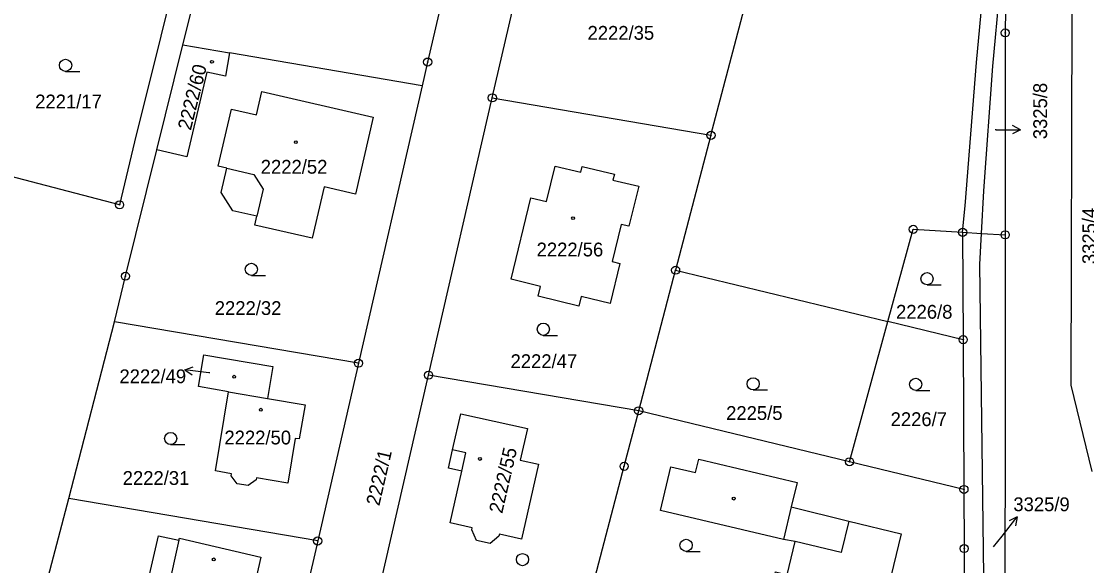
# Model space of a CAD drawing. Extents: x -733394 to -722299, y -1082822 to -1075049.
# Drawn here: x -728113.5 to -727982.2, y -1080117.1 to -1080050 of the extents above; entities that cross this region are included whole.
import ezdxf

# ---------------------------------------------------------------- set-up
doc = ezdxf.new("R2010")
doc.units = 0
for name, color, linetype in [('Hranice parcel', 7, 'Continuous'), ('Parcelní čísla', 7, 'Continuous'), ('Pop  PČ popisy', 7, 'Continuous'), ('Vnitřní kresba', 7, 'Continuous'), ('Značky bodu BP', 7, 'Continuous'), ('Značky budov', 7, 'Continuous'), ('Značky kultur', 7, 'Continuous')]:
    doc.layers.add(name, color=color, linetype=linetype)

msp = doc.modelspace()

# ---------------------------------------------------------------- linework, layer by layer
at = {"layer": 'Hranice parcel'}
for p, q in [((-728028.5, -1080064.02), (-728021.79, -1080038.43)), ((-728055.46, -1080059.4), (-728051.18, -1080040.77)), ((-728096.82, -1080065.82), (-728093.6, -1080052.86)), ((-728093.6, -1080052.86), (-728087.85, -1080053.85)), ((-728064.1, -1080057.92), (-728087.85, -1080053.85)), ((-728064.1, -1080057.92), (-728071.96, -1080092.12)), ((-728063.32, -1080093.59), (-728055.46, -1080059.4)), ((-728055.46, -1080059.4), (-728028.5, -1080064.02)), ((-728028.5, -1080064.02), (-728032.86, -1080080.65)), ((-727997.47, -1080075.98), (-727995.14, -1080076.12)), ((-727997.47, -1080075.98), (-727997.4, -1080089.22)), ((-727995.14, -1080076.12), (-727992.23, -1080076.29)), ((-728037.41, -1080097.98), (-728032.86, -1080080.65)), ((-728032.86, -1080080.65), (-728006.68, -1080086.97)), ((-728107.69, -1080108.81), (-728102.03, -1080087.02)), ((-728071.96, -1080092.12), (-728102.03, -1080087.02)), ((-728011.42, -1080104.27), (-728006.68, -1080086.97)), ((-727997.4, -1080089.22), (-728006.68, -1080086.97)), ((-727997.4, -1080089.22), (-727997.31, -1080107.68)), ((-728071.96, -1080092.12), (-728076.99, -1080114.03)), ((-728069.83, -1080121.9), (-728063.32, -1080093.59)), ((-728037.41, -1080097.98), (-728063.32, -1080093.59)), ((-728087.97, -1080095.65), (-728083.16, -1080096.46)), ((-728011.42, -1080104.27), (-728037.41, -1080097.98)), ((-727997.31, -1080107.68), (-728011.42, -1080104.27)), ((-728113.36, -1080130.56), (-728107.69, -1080108.81)), ((-728076.99, -1080114.03), (-728107.69, -1080108.81)), ((-728076.99, -1080114.03), (-728082.02, -1080135.91))]:
    msp.add_line(p, q, dxfattribs=at)
for points in [[(-727997.47, -1080075.98), (-727997.14, -1080072.72), (-727995.77, -1080055.05), (-727992.88, -1080024.23), (-727989.24, -1079986.88)], [(-728090.08, -1080026.56), (-728096.32, -1080051.79), (-728099.57, -1080064.82), (-728101.42, -1080072.59), (-728130.38, -1080065.04), (-728119.19, -1080019.31)], [(-728093.6, -1080052.86), (-728092.88, -1080049.94), (-728087.37, -1080027.23)], [(-727995.14, -1080076.12), (-727994.87, -1080070.86), (-727993.74, -1080055.5), (-727992.04, -1080036.89)], [(-727992.04, -1080036.89), (-727992.22, -1080051.39), (-727992.23, -1080076.29)], [(-728059.81, -1080039.25), (-728063.43, -1080054.99), (-728064.1, -1080057.92)], [(-727981.48, -1080105.46), (-727984.1, -1080094.81), (-727983.95, -1080048.87), (-727983.62, -1080045.49), (-727981.59, -1080043.33)], [(-728087.85, -1080053.85), (-728088.35, -1080056.74), (-728090.66, -1080056.22), (-728093.14, -1080066.68), (-728096.82, -1080065.82)], [(-728089.26, -1080067.84), (-728087.62, -1080060.78), (-728084.55, -1080061.48), (-728083.88, -1080058.61), (-728070.13, -1080061.77), (-728072.31, -1080071.26), (-728076.2, -1080070.37), (-728077.66, -1080076.69), (-728084.73, -1080075.08), (-728084.48, -1080074), (-728087.46, -1080073.32), (-728088.87, -1080071.07), (-728088.19, -1080068.08), (-728089.26, -1080067.84)], [(-728102.03, -1080087.02), (-728100.69, -1080081.39), (-728096.82, -1080065.82)], [(-728048.76, -1080072.18), (-728047.7, -1080067.81), (-728044.54, -1080068.58), (-728044.36, -1080067.85), (-728040.41, -1080068.81), (-728040.59, -1080069.54), (-728037.41, -1080070.31), (-728038.61, -1080075.24), (-728039.59, -1080075), (-728040.7, -1080079.59), (-728039.73, -1080079.83), (-728040.93, -1080084.75), (-728044.52, -1080083.88), (-728044.81, -1080085.07), (-728049.82, -1080083.86), (-728049.51, -1080082.67), (-728053.15, -1080081.76), (-728050.7, -1080071.71), (-728048.76, -1080072.18)], [(-728006.68, -1080086.97), (-728003.56, -1080075.61), (-727997.47, -1080075.98)], [(-727992.28, -1080179.48), (-727993.15, -1080175.17), (-727994.28, -1080166.67), (-727995.13, -1080156.37), (-727995.24, -1080152.95), (-727994.62, -1080137.51), (-727995.33, -1080079.94), (-727995.14, -1080076.12)], [(-727992.23, -1080076.29), (-727992.27, -1080143.65), (-727992.65, -1080172.17), (-727992.28, -1080179.48)], [(-728087.97, -1080095.65), (-728091.7, -1080094.98), (-728091.04, -1080091.08), (-728082.53, -1080092.52), (-728083.16, -1080096.46)], [(-728083.16, -1080096.46), (-728078.55, -1080097.23), (-728079.26, -1080101.46), (-728079.75, -1080101.38), (-728080.68, -1080106.9), (-728084.54, -1080106.23), (-728084.58, -1080106.48), (-728085.58, -1080107.19), (-728086.93, -1080106.98), (-728087.64, -1080105.99), (-728087.6, -1080105.75), (-728089.6, -1080105.38), (-728087.97, -1080095.65)], [(-728060.35, -1080102.79), (-728059.35, -1080098.34), (-728051.13, -1080100.18), (-728052.01, -1080104.06), (-728049.76, -1080104.57), (-728051.87, -1080113.8), (-728054.59, -1080113.19), (-728054.65, -1080113.43), (-728055.73, -1080114.36), (-728057.4, -1080113.98), (-728057.98, -1080112.65), (-728057.93, -1080112.41), (-728060.66, -1080111.78), (-728059.23, -1080105.44), (-728060.87, -1080105.06), (-728060.35, -1080102.79)], [(-728044.79, -1080126.14), (-728039.21, -1080104.83), (-728037.41, -1080097.98)], [(-728007.56, -1080126.52), (-728009.75, -1080125.99), (-728010.77, -1080130.3), (-728021.41, -1080127.76), (-728020.43, -1080123.68), (-728021.88, -1080123.33), (-728020.56, -1080117.84), (-728019.11, -1080118.19), (-728018.13, -1080114.1), (-728019.57, -1080113.87), (-728034.74, -1080110.27), (-728033.45, -1080104.88), (-728030.39, -1080105.61), (-728030, -1080103.96), (-728017.87, -1080106.83), (-728018.6, -1080109.84), (-728011.52, -1080111.59), (-728005.06, -1080113.14), (-728006.63, -1080119.6), (-728008.13, -1080119.24), (-728008.96, -1080122.69), (-728006.77, -1080123.2), (-728007.56, -1080126.52)], [(-727997.31, -1080107.68), (-727997.28, -1080114.97), (-727997.4, -1080140.66)], [(-728085.07, -1080120.72), (-728086.03, -1080120.51), (-728087.68, -1080127.7), (-728096.76, -1080125.64), (-728096.7, -1080125.36), (-728099.24, -1080124.78), (-728096.63, -1080113.4), (-728094.09, -1080113.95), (-728094.03, -1080113.69), (-728083.98, -1080116.01), (-728085.07, -1080120.72)]]:
    msp.add_lwpolyline(points, dxfattribs=at)
at = {"layer": 'Pop  PČ popisy'}
for p, q in [((-727990.34, -1080063.33), (-727991.34, -1080062.83)), ((-727993.34, -1080063.33), (-727993.46, -1080063.33)), ((-727993.34, -1080063.33), (-727990.34, -1080063.33)), ((-727990.34, -1080063.33), (-727991.34, -1080063.83)), ((-728093.39, -1080092.93), (-728092.33, -1080092.56)), ((-728090.41, -1080093.3), (-728093.39, -1080092.93)), ((-728093.39, -1080092.93), (-728092.46, -1080093.55)), ((-728090.29, -1080093.32), (-728090.41, -1080093.3)), ((-727992.59, -1080113.42), (-727990.74, -1080111.06)), ((-727990.74, -1080111.06), (-727991.75, -1080111.54)), ((-727990.74, -1080111.06), (-727990.96, -1080112.15)), ((-727993.65, -1080114.77), (-727992.59, -1080113.42))]:
    msp.add_line(p, q, dxfattribs=at)
at = {"layer": 'Vnitřní kresba'}
for p, q in [((-728088.19, -1080068.08), (-728084.86, -1080068.85)), ((-728084.86, -1080068.85), (-728083.72, -1080070.67)), ((-728083.72, -1080070.67), (-728084.48, -1080074)), ((-728058.71, -1080103.17), (-728060.35, -1080102.79)), ((-728059.23, -1080105.44), (-728058.71, -1080103.17)), ((-728018.6, -1080109.84), (-728019.57, -1080113.87)), ((-728011.52, -1080111.59), (-728012.45, -1080115.47)), ((-728094.09, -1080113.95), (-728096.7, -1080125.36)), ((-728012.45, -1080115.47), (-728018.13, -1080114.1))]:
    msp.add_line(p, q, dxfattribs=at)
at = {"layer": 'Značky bodu BP'}
for centre, radius in [((-727992.22, -1080051.39), 0.5), ((-727992.22, -1080051.39), 0.0303), ((-728063.43, -1080054.99), 0.5), ((-728063.43, -1080054.99), 0.0303), ((-728055.46, -1080059.4), 0.5), ((-728055.46, -1080059.4), 0.0303), ((-728028.5, -1080064.02), 0.5), ((-728028.5, -1080064.02), 0.0303), ((-728101.42, -1080072.59), 0.5), ((-728101.42, -1080072.59), 0.0303), ((-728003.56, -1080075.61), 0.5), ((-728003.56, -1080075.61), 0.0303), ((-727997.47, -1080075.98), 0.5), ((-727997.47, -1080075.98), 0.0303), ((-727992.23, -1080076.29), 0.5), ((-727992.23, -1080076.29), 0.0303), ((-728032.86, -1080080.65), 0.5), ((-728100.69, -1080081.39), 0.5), ((-728100.69, -1080081.39), 0.0303), ((-728032.86, -1080080.65), 0.0303), ((-727997.4, -1080089.22), 0.5), ((-727997.4, -1080089.22), 0.0303), ((-728071.96, -1080092.12), 0.5), ((-728071.96, -1080092.12), 0.0303), ((-728063.32, -1080093.59), 0.5), ((-728063.32, -1080093.59), 0.0303), ((-728037.41, -1080097.98), 0.5), ((-728037.41, -1080097.98), 0.0303), ((-728011.42, -1080104.27), 0.5), ((-728039.21, -1080104.83), 0.5), ((-728039.21, -1080104.83), 0.0303), ((-728011.42, -1080104.27), 0.0303), ((-727997.31, -1080107.68), 0.5), ((-727997.31, -1080107.68), 0.0303), ((-728076.99, -1080114.03), 0.5), ((-728076.99, -1080114.03), 0.0303), ((-727997.28, -1080114.97), 0.5), ((-727997.28, -1080114.97), 0.0303)]:
    msp.add_circle(centre, radius, dxfattribs=at)
at = {"layer": 'Značky budov'}
for centre in [(-728090.02, -1080054.97), (-728079.69, -1080064.86), (-728045.5, -1080074.23), (-728087.29, -1080093.78), (-728084, -1080097.85), (-728056.98, -1080103.92), (-728025.7, -1080108.81), (-728089.81, -1080116.3)]:
    msp.add_circle(centre, 0.175, dxfattribs=at)
at = {"layer": 'Značky kultur'}
for p, q in [((-728108.07, -1080056.14), (-728106.32, -1080056.14)), ((-728085.17, -1080081.29), (-728083.42, -1080081.29)), ((-728001.86, -1080082.45), (-728000.11, -1080082.45)), ((-728049.17, -1080088.68), (-728047.42, -1080088.68)), ((-728023.29, -1080095.4), (-728021.54, -1080095.4)), ((-728003.26, -1080095.47), (-728001.51, -1080095.47)), ((-728095.12, -1080102.14), (-728093.37, -1080102.14)), ((-728031.57, -1080115.32), (-728029.82, -1080115.32))]:
    msp.add_line(p, q, dxfattribs=at)
for centre in [(-728108.07, -1080055.39), (-728085.17, -1080080.54), (-728001.86, -1080081.7), (-728049.17, -1080087.93), (-728023.29, -1080094.65), (-728003.26, -1080094.72), (-728095.12, -1080101.39), (-728031.57, -1080114.57), (-728051.73, -1080116.33)]:
    msp.add_circle(centre, 0.75, dxfattribs=at)

# ---------------------------------------------------------------- texts
at = {"layer": 'Parcelní čísla'}
for s, p in [('2222/35', (-728043.72, -1080052.24)), ('2221/17', (-728111.82, -1080060.7)), ('2222/52', (-728084.01, -1080068.75)), ('2222/56', (-728050, -1080078.95)), ('2222/32', (-728089.68, -1080086.17)), ('2226/8', (-728005.68, -1080086.63)), ('2222/47', (-728053.21, -1080092.72)), ('2222/49', (-728101.43, -1080094.58)), ('2225/5', (-728026.63, -1080099.11)), ('2226/7', (-728006.35, -1080099.87)), ('2222/50', (-728088.49, -1080102.13)), ('2222/31', (-728101.03, -1080107.12)), ('3325/9', (-727991.22, -1080110.36))]:
    msp.add_text(s, height=1.7, dxfattribs=at).set_placement(p)
for s, rotation, p in [('2222/60', 76, (-728092.63, -1080063.49)), ('3325/8', 90, (-727987.06, -1080064.5)), ('3325/4', 90, (-727981.01, -1080079.9)), ('2222/1', 77, (-728069.39, -1080109.78)), ('2222/55', 77, (-728054.24, -1080110.73))]:
    msp.add_text(s, height=1.7, rotation=rotation, dxfattribs=at).set_placement(p)

doc.saveas('drawing.dxf')
